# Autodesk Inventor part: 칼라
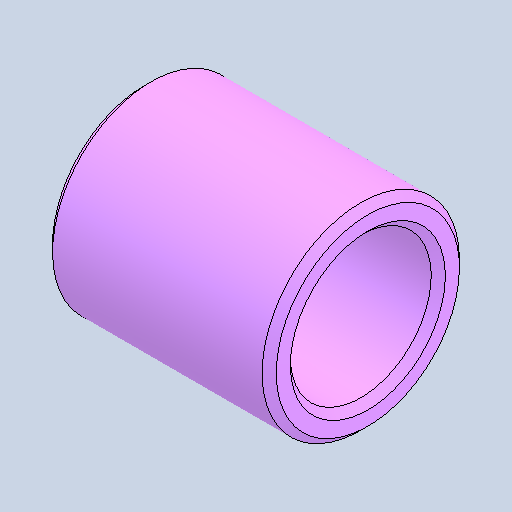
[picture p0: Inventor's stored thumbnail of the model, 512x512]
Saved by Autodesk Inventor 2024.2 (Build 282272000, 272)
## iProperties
Created: 2026-01
Part Number: 칼라
Material: 강철, 연강
Document SubType Name: Modeling
Designer: home
Density: 7.85 g/cm^3
Appearance: 기본값
Author: jhkim
Sending System: Autodesk Inventor 2026
Preprocessor: ST-DEVELOPER v20.1
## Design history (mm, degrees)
feature "솔리드1"
node "솔리드2"
